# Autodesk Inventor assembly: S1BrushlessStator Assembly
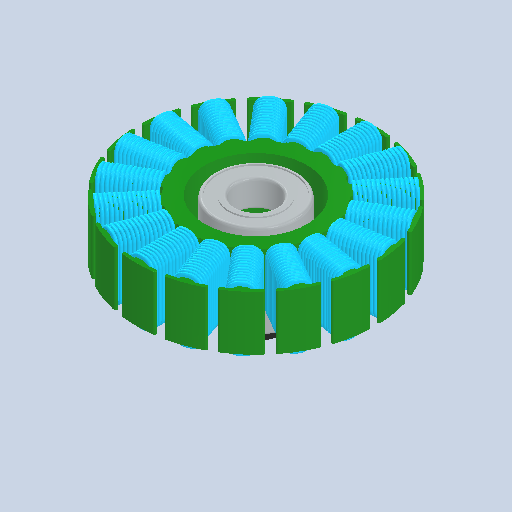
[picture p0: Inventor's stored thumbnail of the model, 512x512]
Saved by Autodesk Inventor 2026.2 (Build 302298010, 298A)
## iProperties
Created: 1601-01
Part Number: S1BrushlessStator Assembly
Document SubType Name: Assembly
Designer: mel
Author: mel
Part Number: Stator Assembly
Sending System: SOLIDWORKS 2023
Last Saved Date: 2025-04-02
last saved by: pierr
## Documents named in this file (6)
- C:\Users\mel\Downloads\18256-itec-20250709t050547z-1-001 (1)\ITEC\Ressources\ITEC00_SW_Appareil_de_massage\S1Appareil_de_massage\S1Appareil_de_massage\S1BrushlessStator Assembly.iam
- C:\Users\mel\Downloads\18256-itec-20250709t050547z-1-001 (1)\ITEC\Ressources\ITEC00_SW_Appareil_de_massage\S1Appareil_de_massage\S1Appareil_de_massage\S1BrushlessIron Core.ipt
- C:\Users\mel\Downloads\18256-itec-20250709t050547z-1-001 (1)\ITEC\Ressources\ITEC00_SW_Appareil_de_massage\S1Appareil_de_massage\S1Appareil_de_massage\S1BrushlessBearing.ipt
- C:\Users\mel\Downloads\18256-itec-20250709t050547z-1-001 (1)\ITEC\Ressources\ITEC00_SW_Appareil_de_massage\S1Appareil_de_massage\S1Appareil_de_massage\S1BrushlessMotor Windings.ipt
- C:\Users\mel\Downloads\18256-itec-20250709t050547z-1-001 (1)\ITEC\Ressources\ITEC00_SW_Appareil_de_massage\S1Appareil_de_massage\S1Appareil_de_massage\S1BrushlessRetaining Washer.ipt
- C:\Users\mel\Downloads\18256-itec-20250709t050547z-1-001 (1)\ITEC\Ressources\ITEC00_SW_Appareil_de_massage\S1Appareil_de_massage\S1Appareil_de_massage\S1BrushlessM3x0.5mm-5mm Button Head Screw.ipt
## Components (23 placed, 23 different names)
1. BrushlessIron Core-1
2. BrushlessBearing-1
3. BrushlessBearing-2
4. BrushlessMotor Windings-1
5. BrushlessMotor Windings-2
6. BrushlessMotor Windings-4
7. BrushlessMotor Windings-6
8. BrushlessMotor Windings-8
9. BrushlessMotor Windings-10
10. BrushlessMotor Windings-12
11. BrushlessMotor Windings-14
12. BrushlessMotor Windings-16
13. BrushlessMotor Windings-20
14. BrushlessMotor Windings-26
15. BrushlessMotor Windings-28
16. BrushlessMotor Windings-30
17. BrushlessMotor Windings-32
18. BrushlessMotor Windings-34
19. BrushlessMotor Windings-36
20. BrushlessMotor Windings-39
21. BrushlessMotor Windings-40
22. BrushlessRetaining Washer-1
23. BrushlessM3x0.5mm-5mm Button Head Screw-1
